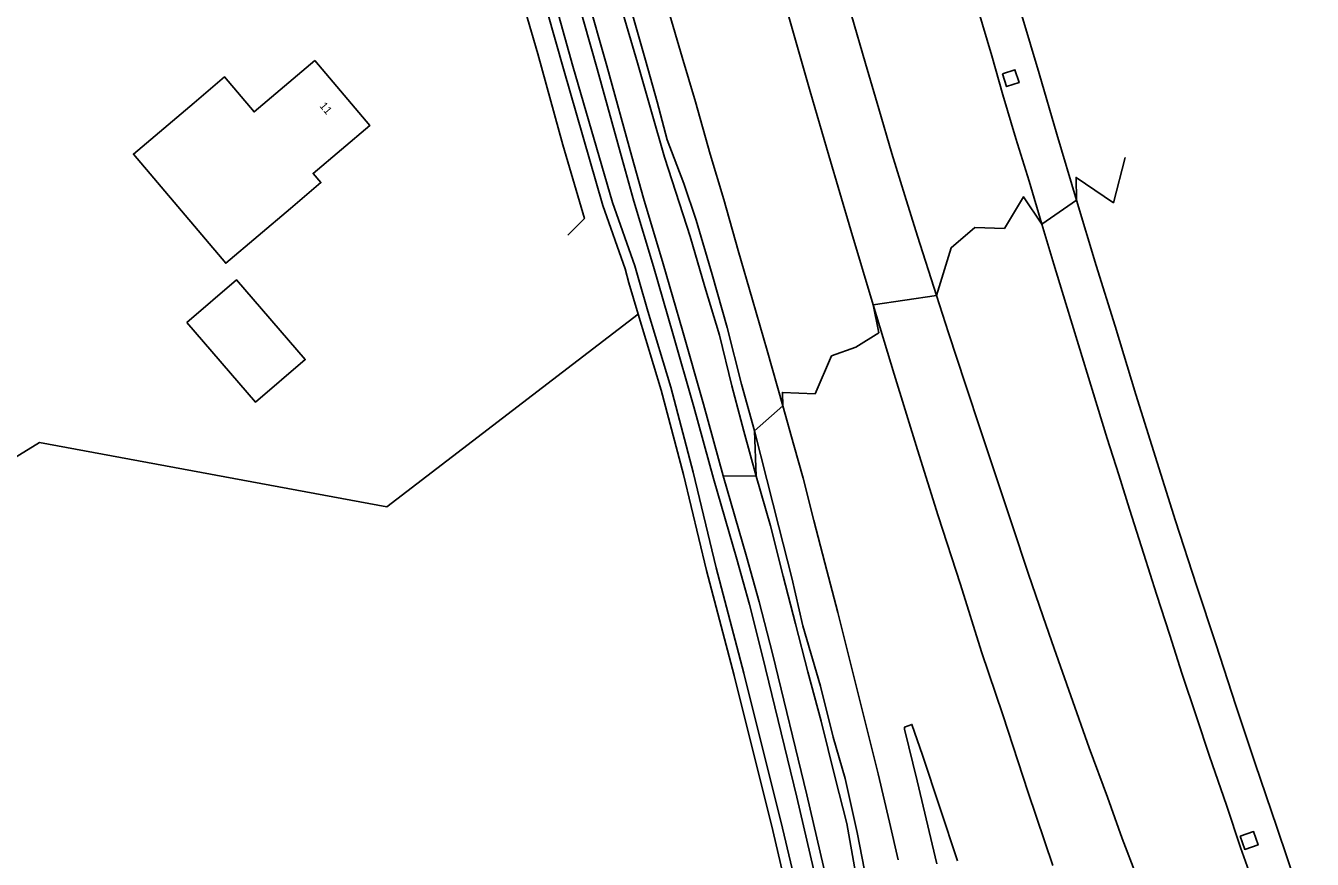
# Model space of a CAD drawing. Extents: x 155209 to 156823, y 385356 to 388482.
# Drawn here: x 156237 to 156397.8, y 385927.8 to 386032 of the extents above; entities that cross this region are included whole.
import ezdxf

# ---------------------------------------------------------------- set-up
doc = ezdxf.new("R2010")
doc.units = 0
for name, color, linetype in [('IMGEO_Berm_groen', 7, 'Continuous'), ('IMGEO_Erf', 7, 'Continuous'), ('IMGEO_Grasland_agrarisch', 7, 'Continuous'), ('IMGEO_Grasland_overig', 7, 'Continuous'), ('IMGEO_Muur', 7, 'Continuous'), ('IMGEO_Pand', 7, 'Continuous'), ('IMGEO_Pand_nummerreeks', 7, 'Continuous'), ('IMGEO_Rijbaan_autosnelweg', 7, 'Continuous'), ('IMGEO_Rijbaan_autoweg', 7, 'Continuous'), ('IMGEO_Waterloop', 7, 'Continuous')]:
    doc.layers.add(name, color=color, linetype=linetype)

msp = doc.modelspace()

# ---------------------------------------------------------------- linework, layer by layer
at = {"layer": 'IMGEO_Berm_groen'}
for points in [[(156328.27, 385975.67), (156326.76, 385981.33), (156325.24, 385986.98), (156323.71, 385993.33), (156321.86, 385999.37), (156320.02, 386005.64), (156318.25, 386011.17), (156316.84, 386015.57), (156315.21, 386021.23), (156313.45, 386027.35), (156311.45, 386034.14)], [(156312.54, 386034.39), (156314.45, 386027.66), (156315.93, 386022.46), (156317.17, 386017.73), (156319.26, 386012.25), (156320.8, 386007.69), (156322.78, 386000.9), (156324.68, 385994.26), (156326.46, 385987.2), (156328.07, 385981.35)], [(156359.07, 386025.96), (156359.58, 386024.37), (156361.15, 386024.87), (156360.63, 386026.47), (156359.07, 386025.96)], [(156363.99, 386007.19), (156368.34, 386010.18)], [(156350.82, 385998.26), (156342.93, 385997.09)], [(156331.64, 385984.47), (156328.07, 385981.35)], [(156328.07, 385981.35), (156328.27, 385975.67)], [(156328.07, 385981.35), (156329.6, 385975.27), (156331.1, 385969.34), (156332.73, 385962.99), (156334.14, 385957), (156336.32, 385949.43), (156337.91, 385943.08), (156339.4, 385937.89), (156340.93, 385931.15), (156342.1, 385924.95)], [(156388.78, 385930.69), (156389.35, 385929.04), (156391.02, 385929.61), (156390.46, 385931.26), (156388.78, 385930.69)]]:
    msp.add_lwpolyline(points, dxfattribs=at)
at = {"layer": 'IMGEO_Erf'}
msp.add_lwpolyline([(156313.52, 385995.94), (156312.39, 385999.87), (156311.9, 386001.59), (156309.14, 386009.51), (156304.19, 386026.59), (156301.15, 386037.36), (156297.83, 386048.46), (156295.21, 386057.96), (156293.36, 386065.81), (156293.1, 386066.52)], dxfattribs=at)
at = {"layer": 'IMGEO_Grasland_agrarisch'}
for points in [[(156185.49, 386016.08), (156220.55, 385968.74), (156238.7, 385979.88), (156282.13, 385971.86), (156313.52, 385995.94)], [(156334.92, 385909.37), (156334.01, 385915.29), (156332.55, 385922.13), (156330.36, 385931.41), (156325.53, 385950.77), (156322.07, 385963.91), (156319.21, 385975.88), (156316.41, 385986.45), (156313.52, 385995.94)]]:
    msp.add_lwpolyline(points, dxfattribs=at)
at = {"layer": 'IMGEO_Grasland_overig'}
for points in [[(156324.17, 385975.73), (156321.69, 385984.67), (156319.09, 385993.88), (156316.65, 386002.24), (156314.19, 386010.42), (156312.73, 386015.64), (156309.64, 386026.95), (156307.08, 386035.94), (156304.49, 386044.8), (156302.39, 386052.33), (156298.72, 386064.89), (156296.33, 386072.74), (156294.62, 386079), (156292.7, 386085.89), (156292.61, 386086.1), (156291.9, 386087.71), (156291.39, 386088.19)], [(156320.63, 385807.71), (156322.68, 385811.31), (156325.02, 385815.45), (156329.01, 385824.01), (156330.72, 385827.88), (156332.8, 385833.73), (156336.02, 385844.45), (156338.23, 385853.44), (156340.13, 385863.33), (156340.97, 385869.12), (156341.5, 385878.27), (156341.63, 385883.09), (156341.67, 385888.44), (156341.76, 385893.69), (156341.21, 385899.75), (156340.61, 385905.11), (156339.5, 385912.98), (156338.23, 385919.74), (156337.1, 385925.1), (156334.61, 385935.86), (156330.31, 385953.51), (156328.66, 385960), (156327.09, 385965.66), (156324.17, 385975.73)], [(156328.27, 385975.67), (156324.17, 385975.73)], [(156328.27, 385975.67), (156330.06, 385969.5), (156331.68, 385963.19), (156333.2, 385957.24), (156334.76, 385951.24), (156336.41, 385945.08), (156338.18, 385938), (156339.63, 385932.28), (156340.72, 385926.15)]]:
    msp.add_lwpolyline(points, dxfattribs=at)
at = {"layer": 'IMGEO_Muur'}
msp.add_lwpolyline([(156292.87, 386056.7), (156297.31, 386041.04), (156300.99, 386028.46), (156304.14, 386017.08), (156306.82, 386007.87), (156304.75, 386005.81)], dxfattribs=at)
at = {"layer": 'IMGEO_Pand'}
for points in [[(156273.12, 386027.63), (156279.99, 386019.51), (156272.91, 386013.52), (156273.88, 386012.37), (156270.07, 386009.14), (156261.98, 386002.3), (156250.44, 386015.94), (156258.02, 386022.35), (156261.84, 386025.58), (156265.53, 386021.21), (156273.12, 386027.63)], [(156257.14, 385994.88), (156263.34, 386000.22), (156271.92, 385990.25), (156265.72, 385984.92), (156257.14, 385994.88)]]:
    msp.add_lwpolyline(points, dxfattribs=at)
at = {"layer": 'IMGEO_Rijbaan_autosnelweg'}
for points in [[(156327.85, 386076.23), (156328.14, 386075.17), (156329.11, 386071.85), (156330.86, 386065.93), (156332.48, 386060.11), (156334.18, 386054.25), (156335.65, 386049.03), (156337.06, 386044.17), (156338.47, 386039.22), (156340.17, 386033.42), (156341.96, 386027.27), (156343.62, 386021.58), (156345.26, 386016.01), (156346.86, 386010.78), (156348.47, 386005.67), (156350.82, 385998.26)], [(156356.01, 386034.1), (156357.74, 386028.21), (156359.13, 386023.36), (156360.76, 386017.9), (156362.39, 386012.55), (156363.99, 386007.19)], [(156361.5, 386033.27), (156363.64, 386026), (156365.86, 386018.43), (156368.34, 386010.18)], [(156368.34, 386010.18), (156368.28, 386013.02), (156372.95, 386009.85), (156374.41, 386015.53)], [(156363.99, 386007.19), (156361.69, 386010.61), (156359.31, 386006.63), (156355.63, 386006.76), (156352.65, 386004.23), (156350.82, 385998.26)], [(156368.34, 386010.18), (156370.78, 386002.02), (156373.14, 385994.43), (156375.73, 385985.9), (156378.39, 385977.41), (156380.72, 385970.09), (156383.34, 385962.03), (156385.73, 385954.75), (156388.24, 385947.01), (156390.64, 385939.77), (156393.35, 385931.83), (156396.09, 385923.79)], [(156390.72, 385924.04), (156388.83, 385929.3), (156387.08, 385934.56), (156384.95, 385940.71), (156383.32, 385945.6), (156381.51, 385951.05), (156379.98, 385955.82), (156378.33, 385960.96), (156376.74, 385965.93), (156374.95, 385971.57), (156373.61, 385975.87), (156372.16, 385980.41), (156370.28, 385986.53), (156368.58, 385992.1), (156367.01, 385997.25), (156365.51, 386002.18), (156363.99, 386007.19)], [(156350.82, 385998.26), (156352.31, 385993.61), (156354.46, 385987.14), (156356.39, 385981.22), (156358.18, 385975.96), (156360.27, 385969.61), (156362.3, 385963.57), (156364.16, 385958.1), (156365.53, 385954.13), (156367.62, 385948.22), (156369.92, 385941.75), (156372.22, 385935.59), (156374.02, 385930.39), (156375.81, 385925.73), (156377.69, 385920.7), (156379.47, 385916.11), (156381.48, 385910.77), (156383.35, 385905.76), (156385.46, 385900.06), (156388.24, 385893.23), (156391.67, 385884.39), (156393.81, 385878.42), (156396.15, 385872.51), (156397.8, 385868.25)]]:
    msp.add_lwpolyline(points, dxfattribs=at)
at = {"layer": 'IMGEO_Rijbaan_autoweg'}
for points in [[(156342.93, 385997.09), (156340.1, 386006.42), (156337.39, 386015.76), (156335.05, 386023.78), (156332.69, 386031.91), (156330.22, 386040.66), (156327.67, 386049.53), (156325.22, 386058.01), (156323.14, 386065.33), (156321.21, 386072.3)], [(156317.29, 386034.03), (156319.05, 386028.06), (156320.69, 386022.45), (156322.54, 386015.92), (156324.23, 386010.26), (156326.05, 386003.89), (156327.84, 385997.73), (156329.68, 385991.39), (156331.64, 385984.47)], [(156342.93, 385997.09), (156343.61, 385993.62), (156340.75, 385991.83), (156337.72, 385990.71), (156335.65, 385985.99), (156331.56, 385986.16), (156331.64, 385984.47)], [(156365.36, 385927.05), (156362.3, 385936.17), (156359.13, 385945.86), (156356.46, 385953.75), (156353.82, 385962.14), (156351.05, 385970.73), (156348.44, 385978.98), (156345.55, 385988.42), (156342.93, 385997.09)], [(156346.04, 385927.76), (156344.95, 385932.45), (156343.54, 385938.5), (156341.9, 385944.97), (156340.24, 385951.66), (156338.48, 385958.65), (156336.85, 385964.86), (156335.51, 385970.14), (156334.15, 385975.44), (156333, 385979.55), (156331.64, 385984.47)], [(156350.88, 385927.24), (156348.41, 385937.62), (156346.82, 385944.08), (156346.83, 385944.33), (156347.75, 385944.67), (156349.06, 385940.84), (156351.25, 385934.28), (156353.45, 385927.61)]]:
    msp.add_lwpolyline(points, dxfattribs=at)
at = {"layer": 'IMGEO_Waterloop'}
for points in [[(156333.78, 385922.41), (156331.58, 385931.7), (156326.75, 385951.08), (156323.29, 385964.22), (156320.43, 385976.19), (156317.62, 385986.79), (156314.73, 385996.29), (156313.6, 386000.22), (156313.1, 386001.97), (156310.34, 386009.9), (156305.39, 386026.93), (156302.36, 386037.71)], [(156305.88, 386035.59), (156308.43, 386026.61), (156311.52, 386015.31), (156312.98, 386010.07), (156315.44, 386001.88), (156317.88, 385993.53), (156320.48, 385984.34), (156322.96, 385975.39), (156325.88, 385965.31), (156327.44, 385959.67), (156329.09, 385953.21), (156333.39, 385935.57), (156335.87, 385924.83)]]:
    msp.add_lwpolyline(points, dxfattribs=at)

# ---------------------------------------------------------------- texts
at = {"layer": 'IMGEO_Pand_nummerreeks'}
msp.add_text('11', height=1, rotation=310.2063, dxfattribs=at).set_placement((156273.65, 386021.93))

doc.saveas('drawing.dxf')
